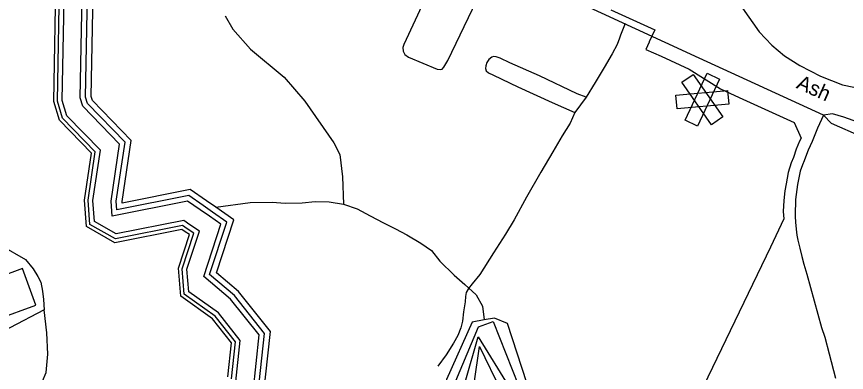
# Model space of a CAD drawing. Extents: x 2260773 to 2342389, y 552869 to 618546.
# Drawn here: x 2290088 to 2293789, y 597561 to 599147 of the extents above; entities that cross this region are included whole.
import ezdxf

# ---------------------------------------------------------------- set-up
doc = ezdxf.new("R2010")
doc.units = 0
for name, color, linetype in [('Exist Boundary Political City Limit New', 7, 'Continuous'), ('Exist Cultural Hospital CELL', 7, 'Continuous'), ('Exist Cultural Warehouse Building Footprint', 7, 'Continuous'), ('Exist Hydrographic Buffer Line', 7, 'Continuous'), ('Exist Hydrographic Creek Single Shore', 7, 'Continuous'), ('Exist Hydrographic Lake Shore', 7, 'Continuous'), ('Exist Hydrographic Misc Water Feature', 7, 'Continuous'), ('Exist Hydrographic River Shore', 7, 'Continuous'), ('Exist Road Non-System Type 51', 7, 'Continuous'), ('Exist Road Primary NC Attributed', 7, 'Continuous'), ('Exist Road Primary NC Label', 7, 'Continuous'), ('Exist Road Secondary Type 51 Attributed', 7, 'Continuous'), ('Map Preparation Boundary City Limit Buffer Line', 7, 'Continuous')]:
    doc.layers.add(name, color=color, linetype=linetype)

msp = doc.modelspace()

# ---------------------------------------------------------------- linework, layer by layer
at = {"layer": 'Exist Boundary Political City Limit New'}
msp.add_lwpolyline([(2292738.2, 599177.5), (2292820.2, 599140.2), (2292934.5, 599088), (2292909.8, 599033.8), (2292909.2, 599032.9), (2292894.5, 599000.4), (2292962, 598969.8), (2293087.8, 598912.6), (2293227.8, 598824.3), (2293310.2, 598786.4), (2293556.5, 598674.9), (2293587.2, 598605.5), (2293580, 598591.3), (2293564.8, 598555.9), (2293553.5, 598518.1), (2293542.2, 598495.4), (2293529.5, 598451.2), (2293519.5, 598400.8), (2293514.5, 598370.5), (2293509.2, 598326.3), (2293506.8, 598278.4), (2293509.8, 598244.7), (2293449.8, 598119.4), (2293151.8, 597500)], dxfattribs=at)
at = {"layer": 'Exist Cultural Hospital CELL'}
for points in [[(2293125, 598658.9), (2293069.9, 598684.7), (2293167.6, 598893.9), (2293222.7, 598868.2)], [(2293237.4, 598699.2), (2293187.6, 598664.4), (2293055.2, 598853.7), (2293105, 598888.5)], [(2293033.9, 598736.2), (2293028.6, 598796.7), (2293258.7, 598816.7), (2293264, 598756.2)]]:
    msp.add_lwpolyline(points, close=True, dxfattribs=at)
at = {"layer": 'Exist Cultural Warehouse Building Footprint'}
for p, q in [((2290115, 598023.9), (2289891.4, 597942.9)), ((2290174, 597861), (2290115, 598023.9)), ((2289950.5, 597780), (2290174, 597861))]:
    msp.add_line(p, q, dxfattribs=at)
at = {"layer": 'Exist Hydrographic Buffer Line'}
for points in [[(2290849, 598201.4), (2290828.4, 598215.7), (2290528.6, 598156), (2290415.2, 598220.3), (2290407, 598328.1), (2290439.1, 598543.5), (2290293.1, 598693.6), (2290270, 598769.9), (2290281.1, 599365.1), (2290094, 599703.5), (2290093, 599870), (2290152.9, 600010.7)], [(2290861.2, 598218.9), (2290833.2, 598238.4), (2290532.2, 598178.5), (2290435.6, 598233.2), (2290428.4, 598327.4), (2290461.7, 598550.8), (2290312, 598704.8), (2290291.3, 598772.9), (2290302.5, 599370.4), (2290115.2, 599709.1), (2290114.3, 599865.7), (2290170.6, 599997.9)], [(2290907.3, 598285.1), (2290851, 598324.2), (2290514.7, 598257.2), (2290509.6, 598324.4), (2290547.4, 598578.4), (2290383.5, 598746.9), (2290372.2, 598784.1), (2290383.6, 599390.5), (2290170.5, 599775.9)], [(2290920.4, 598304.1), (2290856.2, 598348.7), (2290535.7, 598284.9), (2290532.7, 598323.6), (2290571.9, 598586.3), (2290403.9, 598759), (2290395.4, 598787.3), (2290406.7, 599396.2), (2290197.9, 599773.9)], [(2290961.3, 598275.7), (2290920.3, 598304.1)], [(2292186, 595019.3), (2292321.4, 595204.5), (2292305.2, 595422.7), (2292185, 595556.3), (2292196.3, 595868.6), (2292172, 596047.4), (2291947.2, 596356.2), (2291600, 596469.4), (2291646.1, 596536.2), (2291616.2, 596757.9), (2291526.6, 596920), (2291093, 596887.8), (2290971.3, 597034.1), (2290942.8, 597246.4), (2290895.5, 597288.4), (2291164.1, 597459.1), (2291193.4, 597735), (2291059.2, 597903.3), (2290949.1, 597996.6), (2291025.8, 598231), (2290961.3, 598275.7)], [(2290948.1, 598256.8), (2290907.1, 598285.2)], [(2292095.9, 594696.1), (2292164.5, 595028.8), (2292297.8, 595211.3), (2292282.7, 595413.1), (2292161.6, 595547.8), (2292173.2, 595867.4), (2292150, 596038.5), (2291932.9, 596336.6), (2291563.5, 596457.1), (2291622, 596541.9), (2291593.9, 596750.5), (2291513.5, 596895.9), (2291082.9, 596863.9), (2290949.3, 597024.5), (2290921.1, 597234.9), (2290857.3, 597291.5), (2291142.4, 597472.6), (2291169.5, 597728), (2291042.6, 597887.1), (2290922.4, 597989), (2290998.5, 598221.8), (2290948.1, 598256.8)], [(2291046.2, 597532.3), (2291063.7, 597697.2), (2290973, 597810.8), (2290835.4, 597909), (2290826.2, 598023.1), (2290878, 598181.3), (2290849, 598201.4)], [(2291066.3, 597519.8), (2291085.8, 597703.6), (2290987.8, 597826.4), (2290855.9, 597920.6), (2290847.8, 598020.5), (2290903.1, 598189.8), (2290861.2, 598218.9)], [(2292577.4, 596441.3), (2292499.5, 596536.3), (2292356.8, 596887.9), (2292062.3, 597406.7), (2292047.2, 597522.6), (2292147.9, 597764.2), (2292213.1, 597787.9), (2292325.8, 597502.3), (2292377.1, 597437.4), (2292393.3, 597333.3), (2292553.9, 597031), (2292553.9, 596982.1), (2292715.6, 596681.8), (2292723.8, 596566.4), (2292632.8, 596466.2), (2292577.4, 596441.3)], [(2292608.8, 596499.3), (2292534.4, 596557), (2292393.9, 596903), (2292101.1, 597419.7), (2292088.2, 597516.8), (2292146.4, 597719.6), (2292287.9, 597490), (2292339.4, 597420.1), (2292353.9, 597327.1), (2292513.9, 597021), (2292515.1, 596968.2), (2292676.3, 596670.1), (2292682.6, 596580.6), (2292608.8, 596499.3)], [(2292596.1, 596544.7), (2292569, 596577.7), (2292431, 596917.9), (2292139.6, 597432.7), (2292129.4, 597510.9), (2292152.8, 597676.6), (2292249.8, 597477.6), (2292271.9, 597437.6), (2292301.6, 597402.8), (2292314.4, 597321), (2292327.3, 597282.5), (2292473.9, 597010.8), (2292475.5, 596961.3), (2292637.1, 596658.4), (2292641.6, 596594.9), (2292596.1, 596544.7)]]:
    msp.add_lwpolyline(points, dxfattribs=at)
at = {"layer": 'Exist Hydrographic Creek Single Shore'}
for points in [[(2291017.7, 599149.7), (2291052.4, 599090.8), (2291130.9, 599001.7), (2291281.8, 598876.4), (2291373.8, 598769.2), (2291503.6, 598583.4), (2291529, 598531.5), (2291541, 598431.8), (2291545.8, 598310.6)], [(2290975.9, 598296.9), (2291129.2, 598318.1), (2291227.4, 598319), (2291285.6, 598314.8), (2291361.7, 598317), (2291419.3, 598322.8), (2291481.6, 598320.7), (2291545.8, 598310.6), (2291606.5, 598290.4), (2291665.6, 598258), (2291724.6, 598227.7), (2291777.5, 598201.3), (2291828.4, 598174.7), (2291891.5, 598136.5), (2291938.7, 598103.9), (2291976, 598056.9), (2292040.2, 597994.7), (2292087.4, 597952), (2292137.8, 597906.2), (2292166.1, 597856.5), (2292173.7, 597794.8)]]:
    msp.add_lwpolyline(points, dxfattribs=at)
at = {"layer": 'Exist Hydrographic Lake Shore'}
for points in [[(2292173.7, 597794.8), (2292119.8, 597785.4), (2292006, 597528.6), (2292023.8, 597393.7), (2292319.9, 596872.8), (2292464.9, 596515.7), (2292566, 596392.3), (2292656.8, 596433.1), (2292741.7, 596526.6)], [(2292741.7, 596526.6), (2292764.9, 596552.3), (2292754.8, 596693.5), (2292593.8, 596982.1), (2292593.8, 597041.1), (2292432.9, 597339.5), (2292414.8, 597454.7), (2292363.8, 597514.7), (2292277.9, 597778.9), (2292219.8, 597802.9), (2292173.7, 597794.8)]]:
    msp.add_lwpolyline(points, dxfattribs=at)
at = {"layer": 'Exist Hydrographic Misc Water Feature'}
msp.add_lwpolyline([(2293324.9, 599184.1), (2293399.5, 599078.8), (2293455.9, 599019.6), (2293512.7, 598972.1), (2293581.2, 598928.6), (2293673.6, 598881.8), (2293771.7, 598842.7), (2293865.8, 598823.6), (2293993.9, 598824.6), (2294097.9, 598823.5), (2294309.7, 598827.7), (2294383.5, 598824.3), (2294469.5, 598817), (2294581.4, 598790.1), (2294651.9, 598758.7), (2294712.6, 598689.6), (2294759.6, 598614), (2294805.9, 598542.5), (2294842.2, 598492.8), (2294854.3, 598480.9)], dxfattribs=at)
at = {"layer": 'Exist Hydrographic River Shore'}
for points in [[(2290839.8, 598188.1), (2290824.9, 598198.5), (2290525.9, 598139), (2290399.8, 598210.5), (2290390.8, 598328.7), (2290421.9, 598538), (2290278.8, 598685.2), (2290253.8, 598767.7), (2290264.9, 599361), (2290077.9, 599699.3), (2290076.8, 599873.2), (2290141.8, 600026)], [(2290935.1, 598325.2), (2290861.9, 598376.1), (2290559.1, 598315.8), (2290558.6, 598322.7), (2290599.2, 598595.1), (2290426.8, 598772.5), (2290421.2, 598790.9), (2290432.6, 599402.6), (2290227.6, 599773.1), (2290297, 599912)], [(2290975.9, 598296.9), (2290935, 598325.3)], [(2292210.1, 595008.6), (2292347.8, 595197), (2292330.2, 595433.3), (2292211.1, 595565.8), (2292222.1, 595869.8), (2292196.7, 596057.3), (2291963.1, 596378.1), (2291640.8, 596483.2), (2291672.9, 596529.7), (2291641, 596766.1), (2291541.1, 596946.9), (2291104.3, 596914.4), (2290995.8, 597044.9), (2290967.1, 597259.3), (2290938.1, 597285), (2291188.4, 597444.1), (2291220.2, 597742.8), (2291077.8, 597921.3), (2290979, 598005), (2291056.2, 598241.2), (2290975.9, 598296.9)], [(2291030.9, 597541.8), (2291046.9, 597692.3), (2290961.8, 597799), (2290819.9, 597900.2), (2290809.9, 598025), (2290858.9, 598174.9), (2290839.8, 598188.1)]]:
    msp.add_lwpolyline(points, dxfattribs=at)
at = {"layer": 'Exist Road Non-System Type 51'}
msp.add_line((2292627.9, 598788.3), (2292577.1, 598718.6), dxfattribs=at)
for points in [[(2291996.2, 599413), (2291815.1, 599023), (2291811.2, 599009.1), (2291811.5, 598993.1), (2291819.6, 598977.1), (2291835.7, 598965.2), (2291964.2, 598912.4), (2291978.1, 598910.5), (2291986.2, 598912.8), (2291993.9, 598920.8), (2292011.7, 598950.8), (2292121.6, 599179.9), (2292183.7, 599325.5)], [(2292801.5, 599116.4), (2292781.7, 599064.2), (2292776.8, 599051.2)], [(2292776.8, 599051.2), (2292765.8, 599022.1), (2292744, 598981.4), (2292709.2, 598920.4), (2292668.5, 598853.6), (2292627.9, 598788.3)], [(2292627.9, 598788.3), (2292588.7, 598802.8), (2292420.3, 598882.7), (2292288.3, 598940.8), (2292244.7, 598961.1), (2292227.3, 598966.9), (2292214.3, 598968.4), (2292207, 598965.5), (2292193.9, 598955.3), (2292185.2, 598942.2), (2292180.9, 598927.7), (2292179.4, 598914.6), (2292182.3, 598904.5), (2292192.5, 598895.8), (2292214.3, 598885.6), (2292323.1, 598833.3), (2292476.9, 598763.6), (2292577.1, 598718.6)], [(2292577.1, 598718.6), (2292556.8, 598672.1), (2292520.5, 598615.5), (2292479.8, 598544.3), (2292426.1, 598452.9), (2292362.3, 598342.5), (2292307.1, 598240.9), (2292268, 598177), (2292214.3, 598094.2), (2292153.3, 597996.9), (2292119.9, 597956.2), (2292104, 597934.5), (2292093.8, 597917), (2292089.4, 597899.6), (2292088, 597874.9), (2292080.7, 597831.4), (2292076.4, 597789.2), (2292069.1, 597758.8), (2292056.1, 597725.4), (2292037.2, 597690.5), (2292003.8, 597639.7), (2291966.1, 597588.9)], [(2289897.3, 598259.4), (2289933.8, 598213.7), (2290018.6, 598126.6), (2290127.3, 598063.7), (2290162.1, 598023), (2290182.4, 597988.2), (2290195.5, 597963.5), (2290204.3, 597922.5), (2290208.6, 597886.5), (2290211.5, 597840.1)], [(2290211.5, 597840.1), (2290057.6, 597760.2), (2289822.5, 597638.2), (2289722.4, 597587.4)], [(2291082.8, 595921.8), (2291021.3, 595981.4), (2290993.7, 596017.7), (2290963.2, 596056.9), (2290947.3, 596101.9), (2290916.8, 596160), (2290879.1, 596212.2), (2290590.2, 596511.4), (2290458.2, 596653.7), (2290407.4, 596730.7), (2290273.9, 596967.4), (2290202.7, 597092.2), (2290149, 597186.6), (2290120, 597247.6), (2290117.1, 597281), (2290120, 597311.5), (2290134.5, 597359.4), (2290170.8, 597445.1), (2290220.2, 597559.8), (2290227.4, 597642.6), (2290222.2, 597736.8), (2290211.5, 597840.1)]]:
    msp.add_lwpolyline(points, dxfattribs=at)
at = {"layer": 'Exist Road Primary NC Attributed'}
for points in [[(2293686.4, 598707.2), (2293131.7, 598961.1), (2292261.1, 599364.6), (2291655.3, 599643.2), (2291477, 599700.2), (2291388.5, 599717.7), (2291249.1, 599724.9), (2291128.7, 599704.6), (2290992.3, 599668.3), (2290873.4, 599627.5)], [(2294330.6, 598506.1), (2294225.9, 598543.4), (2294154.5, 598567), (2294039.4, 598606.7), (2293922.7, 598646.2), (2293776.9, 598698.9), (2293726.9, 598713.9), (2293686.4, 598707.2)], [(2294307.6, 598447.9), (2294151.6, 598500.7), (2294043, 598537.7), (2293930.9, 598581), (2293858.3, 598611.2), (2293722.4, 598669.5), (2293686.4, 598707.2)]]:
    msp.add_lwpolyline(points, dxfattribs=at)
at = {"layer": 'Exist Road Secondary Type 51 Attributed'}
msp.add_lwpolyline([(2293686.4, 598707.2), (2293660.6, 598649.1), (2293636.5, 598590), (2293618.1, 598551.1), (2293611.2, 598532.6), (2293600.2, 598504), (2293592.8, 598485.3), (2293582.3, 598457.9), (2293577.9, 598436.1), (2293570.2, 598398.8), (2293562, 598331.9), (2293562.3, 598309.3), (2293560.8, 598284.6), (2293561, 598255.6), (2293561.8, 598230), (2293564.5, 598199.6), (2293568.4, 598172.7), (2293572.8, 598149.7), (2293581, 598114.1), (2293590, 598077.5), (2293599.2, 598043.4), (2293612.7, 597998.1), (2293678.5, 597761.3), (2293692.7, 597717.8), (2293711.8, 597644), (2293740.7, 597535.5)], dxfattribs=at)
at = {"layer": 'Map Preparation Boundary City Limit Buffer Line'}
msp.add_lwpolyline([(2292738.2, 599177.5), (2292820.2, 599140.2), (2292934.5, 599088), (2292909.8, 599033.8), (2292909.2, 599032.9), (2292894.5, 599000.4), (2292962, 598969.8), (2293087.8, 598912.6), (2293227.8, 598824.3), (2293310.2, 598786.4), (2293556.5, 598674.9), (2293587.2, 598605.5), (2293580, 598591.3), (2293564.8, 598555.9), (2293553.5, 598518.1), (2293542.2, 598495.4), (2293529.5, 598451.2), (2293519.5, 598400.8), (2293514.5, 598370.5), (2293509.2, 598326.3), (2293506.8, 598278.4), (2293509.8, 598244.7), (2293449.8, 598119.4), (2293151.8, 597500)], dxfattribs=at)

# ---------------------------------------------------------------- texts
at = {"layer": 'Exist Road Primary NC Label'}
msp.add_text('Ash', height=65.62, rotation=335.7872, dxfattribs=at).set_placement((2293561.8, 598829.4))

doc.saveas('drawing.dxf')
